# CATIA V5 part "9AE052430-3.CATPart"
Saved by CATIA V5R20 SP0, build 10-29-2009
Part number: 9AE052430-3
Revision: ANY
Definition: UNKNOWN
Nomenclature: 9AE052430-3
Source: Unknown
Bounding box of the stored display mesh (mm): x -14.75 to 14.75, y 0 to 68.999, z -14.75 to 14.75
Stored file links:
  C:\Users\Utente\Desktop\IO LAVORO\3D X SITO CF\CUMSA\3D files AE\AE 052430\9AE052430-3.CATPart
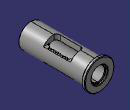
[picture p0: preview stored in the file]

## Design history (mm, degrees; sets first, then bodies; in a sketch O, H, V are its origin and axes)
Body1 "Cortar-Barrer1" (main body)
  Solid1: solid without history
